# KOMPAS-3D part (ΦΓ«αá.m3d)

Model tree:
1. Эскиз:7
2. Операция выдавливания:5
     Расстояние 1 = 10.8; Расстояние 2 = 6.8
3. Эскиз:10
4. Операция выдавливания:6
     Расстояние 1 = 1; Расстояние 2 = 6.8
5. Эскиз:11
6. Операция выдавливания:8
     Расстояние 1 = 1; Расстояние 2 = 6.8
7. Скругление:3
     Радиус = 1
8. Эскиз:12
9. Вырезать элемент выдавливания:7
     Расстояние 1 = 1
10. Эскиз:13
11. Операция выдавливания:9
     Расстояние 1 = 1; Расстояние 2 = 6.8
12. Скругление:4
     Радиус = 0.1
13. Эскиз:14
14. Операция выдавливания:10
     Расстояние 1 = 0.3; Расстояние 2 = 6.8
15. Эскиз:15
16. Операция выдавливания:11
     Расстояние 1 = 0.5; Расстояние 2 = 6.8
17. Скругление:5
     Радиус = 0.5
18. Эскиз:16
19. Операция выдавливания:12
     Расстояние 1 = 0.5; Расстояние 2 = 6.8
20. Скругление:6
     Радиус = 0.2
21. Эскиз:17
22. Вырезать элемент выдавливания:8
     Расстояние 1 = 2
23. Эскиз:18
24. Вырезать элемент выдавливания:9
     Расстояние 1 = 0.2
25. Эскиз:19
26. Вырезать элемент выдавливания:10
     Расстояние 1 = 0.1
27. Эскиз:22
28. Вырезать элемент выдавливания:11
     Расстояние 1 = 1
29. Эскиз:23
30. Вырезать элемент выдавливания:12
     Расстояние 1 = 1
31. Эскиз:26
32. Вырезать элемент выдавливания:13
     Расстояние 1 = 20
33. Эскиз:27
34. Вырезать элемент выдавливания:14
     Расстояние 1 = 11.6061
35. Эскиз:28
36. Операция выдавливания:15
     Расстояние 1 = 1.5; Расстояние 2 = 20.5
37. Скругление:7
     Радиус = 0.3
38. Эскиз:29
39. Вырезать элемент выдавливания:15
     Расстояние 1 = 1
40. Эскиз:30
41. Вырезать элемент выдавливания:16
     Расстояние 1 = 1
42. Эскиз:31
43. Операция выдавливания:16
     Расстояние 1 = 1.5; Расстояние 2 = 14.1
44. Скругление:8
     Радиус = 0.5
45. Эскиз:32
46. Операция выдавливания:17
     Расстояние 1 = 1; Расстояние 2 = 16.5
47. Эскиз:33
48. Операция выдавливания:18
     Расстояние 1 = 1; Расстояние 2 = 1
49. Скругление:9
     Радиус = 0.5
50. Эскиз:34
51. Операция выдавливания:19
     Расстояние 1 = 1; Расстояние 2 = 0.7
52. Скругление:10
     Радиус = 0.5
53. Эскиз:35
54. Операция выдавливания:20
     Расстояние 1 = 1; Расстояние 2 = 0.7
55. Скругление:11
     Радиус = 0.5
56. Эскиз:36
57. Операция выдавливания:21
     Расстояние 1 = 1; Расстояние 2 = 0.7
58. Эскиз:37
59. Операция выдавливания:22
     Расстояние 1 = 1; Расстояние 2 = 0.7
60. Скругление:12
     Радиус = 0.5
61. Эскиз:38
62. Операция выдавливания:23
     Расстояние 1 = 2.5; Расстояние 2 = 2.5
63. Эскиз:39
64. Операция выдавливания:24
     Расстояние 1 = 2.5; Расстояние 2 = 2.5
65. Эскиз:40
66. Операция выдавливания:25
     Расстояние 1 = 0.5; Расстояние 2 = 2.5
67. Эскиз:41
68. Операция выдавливания:26
     Расстояние 1 = 0.5; Расстояние 2 = 2.5
69. Скругление:13
     Радиус = 1
70. Скругление:14
     Радиус = 0.2
71. Эскиз:42
72. Операция выдавливания:27
     Расстояние 1 = 0.5; Расстояние 2 = 2.5
73. Эскиз:43
74. Вырезать элемент выдавливания:17
     Расстояние 1 = 1
75. Эскиз:44
76. Операция выдавливания:28
     Расстояние 1 = 0.5; Расстояние 2 = 2.5
77. Скругление:15
     Радиус = 0.5

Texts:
  stalker61
  Сплав АЛ8  ГОСТ 1583-93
